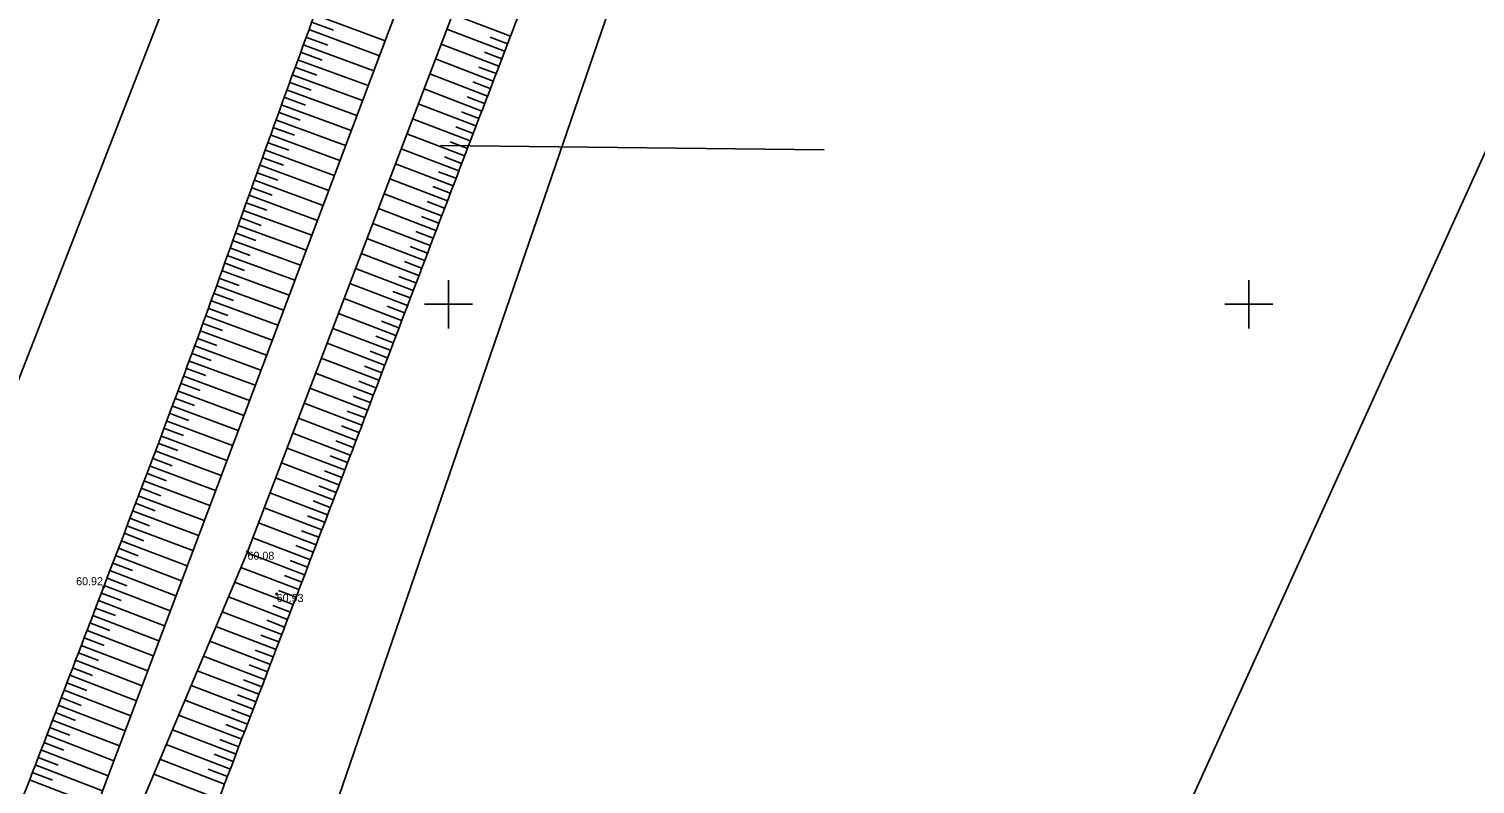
# Model space of a CAD drawing. Extents: x 616607 to 617499, y 408385 to 409695.
# Drawn here: x 617123.8 to 617214.1, y 408870 to 408917.2 of the extents above; entities that cross this region are included whole.
import ezdxf

# ---------------------------------------------------------------- set-up
doc = ezdxf.new("R2010")
doc.units = 0
for name, color, linetype in [('DREN_VADP_####_####_#', 7, 'Continuous'), ('GEOD_ELEM_####_####_#', 7, 'Continuous'), ('HIDG_GRAV_####_####_#', 7, 'Continuous'), ('RAMI_PLAN_####_TKST_#', 7, 'Continuous'), ('RAMI_UZMR_####_####_#', 7, 'Continuous'), ('RELJ_AATZ_####_TKST_#', 7, 'Continuous'), ('RELJ_ELEM_####_####_#', 7, 'Continuous'), ('RELJ_NOGA_####_####_#', 7, 'Continuous')]:
    doc.layers.add(name, color=color, linetype=linetype)

# ---------------------------------------------------------------- blocks, each defined once
blk = doc.blocks.new('PKT')
at = {"layer": 'RELJ_ELEM_####_####_#'}
blk.add_circle((0, 0), 0.05, dxfattribs=at)
blk = doc.blocks.new('KRUSTS')
at = {"layer": 'GEOD_ELEM_####_####_#'}
for p, q in [((0, 1.5), (0, 0)), ((-1.5, 0), (0, 0)), ((0, 0), (0, -1.5)), ((0, 0), (1.5, 0))]:
    blk.add_line(p, q, dxfattribs=at)

msp = doc.modelspace()

# ---------------------------------------------------------------- linework, layer by layer
at = {"layer": 'DREN_VADP_####_####_#'}
msp.add_lwpolyline([(617149.515, 408909.922), (617173.463, 408909.645)], dxfattribs=at)
at = {"layer": 'HIDG_GRAV_####_####_#'}
msp.add_lwpolyline([(616957.708, 408604.801), (616964.717, 408618.582), (616997.814, 408672.816), (617082.506, 408751.106), (617088.497, 408760.889), (617116.937, 408835.934), (617137.451, 408884.548), (617152.78, 408924.733), (617163.79, 408955.542), (617160.997, 408956.152), (617115.742, 408836.043), (617088.001, 408760.943), (617081.506, 408751.106), (616997.147, 408673.705), (616963.717, 408618.582), (616956.708, 408604.801)], dxfattribs=at)
at = {"layer": 'RAMI_PLAN_####_TKST_#'}
msp.add_line((617158.243, 408784.967), (617287, 409068.676), dxfattribs=at)
at = {"layer": 'RAMI_UZMR_####_####_#'}
for points in [[(617191.828, 409115.62), (617145.545, 408952.8), (617072.809, 408766.141), (616965.332, 408652.076), (616939.432, 408594.661), (616924.839, 408592.467), (616706.433, 408526.081), (616666.426, 408467.691)], [(616666.426, 408467.691), (616675.529, 408457.882), (616687.228, 408463.356), (616723.888, 408465.775), (616753.554, 408507.232), (616948.282, 408568.831), (616981.528, 408608.531), (617014.563, 408672.892), (617101.571, 408748.246), (617213.472, 409074.039)]]:
    msp.add_lwpolyline(points, dxfattribs=at)
at = {"layer": 'RELJ_NOGA_####_####_#'}
for p, q in [((617141.507, 408917.605), (617142.815, 408917.122)), ((617141.68, 408918.074), (617146.042, 408916.461)), ((617153.87, 408916.742), (617150.261, 408918.128)), ((617141.105, 408916.514), (617141.106, 408916.514)), ((617141.161, 408916.667), (617142.467, 408916.185)), ((617141.278, 408916.983), (617141.278, 408916.983)), ((617141.334, 408917.136), (617145.691, 408915.528)), ((617153.512, 408915.809), (617149.904, 408917.193)), ((617153.691, 408916.275), (617152.608, 408916.691)), ((617140.815, 408915.728), (617142.12, 408915.248)), ((617140.932, 408916.045), (617140.932, 408916.045)), ((617140.988, 408916.197), (617145.339, 408914.594)), ((617153.153, 408914.875), (617149.547, 408916.258)), ((617153.332, 408915.342), (617152.25, 408915.757)), ((617140.47, 408914.79), (617141.772, 408914.311)), ((617140.587, 408915.107), (617140.587, 408915.107)), ((617140.643, 408915.259), (617144.987, 408913.66)), ((617140.759, 408915.576), (617140.76, 408915.576)), ((617152.795, 408913.941), (617149.191, 408915.323)), ((617152.974, 408914.408), (617151.893, 408914.823)), ((617140.125, 408913.851), (617141.425, 408913.374)), ((617140.242, 408914.168), (617140.242, 408914.168)), ((617140.298, 408914.32), (617144.635, 408912.726)), ((617140.414, 408914.637), (617140.415, 408914.637)), ((617152.437, 408913.008), (617148.834, 408914.389)), ((617152.616, 408913.474), (617151.535, 408913.889)), ((617139.781, 408912.912), (617141.079, 408912.436)), ((617139.897, 408913.229), (617139.897, 408913.229)), ((617139.953, 408913.382), (617144.283, 408911.792)), ((617140.069, 408913.699), (617140.07, 408913.698)), ((617152.08, 408912.074), (617148.478, 408913.454)), ((617152.259, 408912.541), (617151.178, 408912.955)), ((617139.553, 408912.29), (617139.553, 408912.29)), ((617139.609, 408912.443), (617143.931, 408910.858)), ((617139.725, 408912.76), (617139.726, 408912.76)), ((617151.722, 408911.14), (617148.121, 408912.519)), ((617151.901, 408911.607), (617150.82, 408912.021)), ((617139.209, 408911.351), (617139.209, 408911.351)), ((617139.265, 408911.504), (617143.579, 408909.924)), ((617139.381, 408911.821), (617139.382, 408911.821)), ((617139.436, 408911.973), (617140.732, 408911.499)), ((617151.364, 408910.206), (617147.764, 408911.584)), ((617138.865, 408910.412), (617138.865, 408910.412)), ((617138.921, 408910.565), (617143.227, 408908.988)), ((617139.037, 408910.882), (617139.038, 408910.882)), ((617139.093, 408911.034), (617140.386, 408910.561)), ((617151.007, 408909.272), (617147.408, 408910.65)), ((617151.543, 408910.673), (617150.463, 408911.087)), ((617138.521, 408909.473), (617138.521, 408909.473)), ((617138.577, 408909.626), (617142.874, 408908.052)), ((617138.693, 408909.943), (617138.694, 408909.943)), ((617138.749, 408910.095), (617140.039, 408909.623)), ((617150.65, 408908.338), (617147.052, 408909.715)), ((617151.186, 408909.739), (617150.106, 408910.152)), ((617138.178, 408908.534), (617138.178, 408908.534)), ((617138.233, 408908.687), (617142.522, 408907.118)), ((617138.349, 408909.004), (617138.35, 408909.003)), ((617138.405, 408909.156), (617139.693, 408908.685)), ((617150.292, 408907.404), (617146.695, 408908.78)), ((617150.828, 408908.805), (617149.749, 408909.218)), ((617137.834, 408907.595), (617137.834, 408907.595)), ((617137.89, 408907.748), (617142.169, 408906.182)), ((617138.006, 408908.065), (617138.007, 408908.064)), ((617138.062, 408908.217), (617139.347, 408907.747)), ((617149.935, 408906.47), (617146.338, 408907.846)), ((617150.471, 408907.871), (617149.391, 408908.284)), ((617137.491, 408906.656), (617137.491, 408906.656)), ((617137.546, 408906.808), (617141.817, 408905.246)), ((617137.662, 408907.125), (617137.663, 408907.125)), ((617137.718, 408907.278), (617139.001, 408906.809)), ((617149.578, 408905.536), (617145.982, 408906.911)), ((617150.114, 408906.937), (617149.034, 408907.35)), ((617137.147, 408905.717), (617137.147, 408905.717)), ((617137.203, 408905.869), (617141.464, 408904.311)), ((617137.319, 408906.186), (617137.32, 408906.186)), ((617137.375, 408906.339), (617138.654, 408905.871)), ((617149.221, 408904.602), (617145.625, 408905.976)), ((617149.756, 408906.003), (617148.678, 408906.416)), ((617136.804, 408904.778), (617136.804, 408904.778)), ((617136.859, 408904.93), (617141.112, 408903.375)), ((617136.975, 408905.247), (617136.976, 408905.247)), ((617137.031, 408905.4), (617138.308, 408904.933)), ((617148.864, 408903.668), (617145.269, 408905.042)), ((617149.399, 408905.069), (617148.321, 408905.481)), ((617136.516, 408903.991), (617140.759, 408902.439)), ((617136.632, 408904.308), (617136.633, 408904.308)), ((617136.688, 408904.46), (617137.962, 408903.994)), ((617148.507, 408902.734), (617144.912, 408904.107)), ((617149.042, 408904.135), (617147.964, 408904.547)), ((617136.172, 408903.052), (617140.406, 408901.503)), ((617136.288, 408903.369), (617136.289, 408903.369)), ((617136.344, 408903.521), (617137.616, 408903.056)), ((617136.46, 408903.838), (617136.46, 408903.838)), ((617148.15, 408901.8), (617144.556, 408903.172)), ((617148.685, 408903.201), (617147.607, 408903.613)), ((617135.829, 408902.113), (617140.053, 408900.565)), ((617135.945, 408902.43), (617135.946, 408902.429)), ((617136.001, 408902.582), (617137.269, 408902.117)), ((617136.117, 408902.899), (617136.117, 408902.899)), ((617147.793, 408900.865), (617144.199, 408902.238)), ((617148.328, 408902.267), (617147.25, 408902.679)), ((617135.485, 408901.174), (617139.7, 408899.629)), ((617135.601, 408901.491), (617135.602, 408901.49)), ((617135.657, 408901.643), (617136.923, 408901.179)), ((617135.773, 408901.96), (617135.773, 408901.96)), ((617147.436, 408899.931), (617143.843, 408901.304)), ((617147.972, 408901.333), (617146.893, 408901.744)), ((617135.257, 408900.552), (617135.258, 408900.552)), ((617135.312, 408900.704), (617136.576, 408900.241)), ((617135.429, 408901.021), (617135.429, 408901.021)), ((617147.08, 408898.997), (617143.486, 408900.369)), ((617147.615, 408900.398), (617146.537, 408900.81)), ((617134.912, 408899.613), (617134.913, 408899.613)), ((617134.968, 408899.765), (617136.229, 408899.303)), ((617135.084, 408900.082), (617135.085, 408900.082)), ((617135.14, 408900.235), (617139.347, 408898.691)), ((617146.723, 408898.063), (617143.13, 408899.434)), ((617147.258, 408899.464), (617146.18, 408899.876)), ((617134.567, 408898.674), (617134.568, 408898.674)), ((617134.623, 408898.827), (617135.882, 408898.364)), ((617134.74, 408899.144), (617134.74, 408899.144)), ((617134.796, 408899.296), (617138.994, 408897.755)), ((617146.367, 408897.129), (617142.773, 408898.5)), ((617146.901, 408898.53), (617145.823, 408898.941)), ((617134.222, 408897.736), (617134.223, 408897.735)), ((617134.278, 408897.888), (617135.534, 408897.426)), ((617134.395, 408898.205), (617134.395, 408898.205)), ((617134.451, 408898.357), (617138.641, 408896.817)), ((617146.01, 408896.194), (617142.417, 408897.565)), ((617146.545, 408897.596), (617145.467, 408898.007)), ((617133.877, 408896.797), (617133.878, 408896.797)), ((617133.933, 408896.95), (617135.187, 408896.488)), ((617134.05, 408897.267), (617134.05, 408897.266)), ((617134.106, 408897.419), (617138.288, 408895.88)), ((617146.188, 408896.661), (617145.11, 408897.073)), ((617133.531, 408895.859), (617133.532, 408895.859)), ((617133.587, 408896.011), (617134.838, 408895.55)), ((617133.704, 408896.328), (617133.704, 408896.328)), ((617133.76, 408896.481), (617137.934, 408894.942)), ((617145.654, 408895.26), (617142.06, 408896.631)), ((617145.832, 408895.727), (617144.754, 408896.138)), ((617133.185, 408894.921), (617133.186, 408894.921)), ((617133.241, 408895.073), (617134.49, 408894.612)), ((617133.358, 408895.39), (617133.358, 408895.39)), ((617133.414, 408895.542), (617137.581, 408894.003)), ((617145.297, 408894.326), (617141.704, 408895.697)), ((617145.475, 408894.793), (617144.397, 408895.204)), ((617132.838, 408893.983), (617132.839, 408893.983)), ((617132.894, 408894.135), (617134.141, 408893.674)), ((617133.011, 408894.452), (617133.012, 408894.452)), ((617133.068, 408894.604), (617137.227, 408893.065)), ((617144.94, 408893.391), (617141.348, 408894.762)), ((617145.119, 408893.859), (617144.041, 408894.27)), ((617132.49, 408893.045), (617132.491, 408893.045)), ((617132.547, 408893.198), (617133.792, 408892.736)), ((617132.664, 408893.514), (617132.664, 408893.514)), ((617132.72, 408893.666), (617136.874, 408892.129)), ((617144.584, 408892.457), (617140.991, 408893.828)), ((617144.762, 408892.924), (617143.684, 408893.336)), ((617132.199, 408892.26), (617133.442, 408891.798)), ((617132.316, 408892.577), (617132.317, 408892.577)), ((617132.373, 408892.729), (617136.521, 408891.19)), ((617144.227, 408891.523), (617140.635, 408892.894)), ((617144.406, 408891.99), (617143.328, 408892.401)), ((617131.85, 408891.323), (617133.092, 408890.861)), ((617131.968, 408891.639), (617131.968, 408891.639)), ((617132.024, 408891.791), (617136.167, 408890.251)), ((617132.142, 408892.108), (617132.143, 408892.108)), ((617143.871, 408890.589), (617140.278, 408891.959)), ((617144.049, 408891.056), (617142.971, 408891.467)), ((617131.501, 408890.386), (617132.741, 408889.923)), ((617131.619, 408890.702), (617131.619, 408890.702)), ((617131.676, 408890.854), (617135.813, 408889.311)), ((617131.794, 408891.171), (617131.794, 408891.17)), ((617143.514, 408889.654), (617139.922, 408891.025)), ((617143.693, 408890.121), (617142.615, 408890.533)), ((617131.151, 408889.449), (617132.39, 408888.985)), ((617131.269, 408889.765), (617131.269, 408889.765)), ((617131.326, 408889.917), (617135.458, 408888.371)), ((617131.444, 408890.234), (617131.445, 408890.233)), ((617143.158, 408888.72), (617139.566, 408890.091)), ((617143.336, 408889.187), (617142.258, 408889.598)), ((617130.8, 408888.513), (617132.038, 408888.048)), ((617130.919, 408888.829), (617130.919, 408888.829)), ((617130.975, 408888.981), (617135.106, 408887.435)), ((617131.094, 408889.297), (617131.095, 408889.297)), ((617142.801, 408887.786), (617139.209, 408889.156)), ((617142.98, 408888.253), (617141.902, 408888.664)), ((617130.567, 408887.893), (617130.568, 408887.892)), ((617130.624, 408888.044), (617134.752, 408886.496)), ((617130.743, 408888.361), (617130.744, 408888.36)), ((617142.445, 408886.851), (617138.853, 408888.222)), ((617142.623, 408887.319), (617141.545, 408887.73)), ((617130.215, 408886.957), (617130.215, 408886.956)), ((617130.272, 408887.108), (617134.397, 408885.554)), ((617130.391, 408887.424), (617130.392, 408887.424)), ((617130.448, 408887.576), (617131.686, 408887.111)), ((617142.088, 408885.917), (617138.496, 408887.288)), ((617142.267, 408886.384), (617141.189, 408886.795)), ((617129.862, 408886.021), (617129.862, 408886.021)), ((617129.92, 408886.173), (617134.044, 408884.616)), ((617130.039, 408886.489), (617130.04, 408886.488)), ((617130.096, 408886.641), (617131.334, 408886.174)), ((617141.732, 408884.983), (617138.14, 408886.353)), ((617141.91, 408885.45), (617140.832, 408885.861)), ((617129.508, 408885.086), (617129.509, 408885.086)), ((617129.566, 408885.237), (617133.689, 408883.674)), ((617129.685, 408885.553), (617129.686, 408885.553)), ((617129.743, 408885.705), (617130.98, 408885.237)), ((617141.375, 408884.049), (617137.784, 408885.419)), ((617141.554, 408884.516), (617140.476, 408884.927)), ((617129.153, 408884.151), (617129.154, 408884.151)), ((617129.211, 408884.302), (617133.335, 408882.735)), ((617129.331, 408884.618), (617129.332, 408884.618)), ((617129.389, 408884.77), (617130.626, 408884.301)), ((617141.019, 408883.114), (617137.425, 408884.486)), ((617141.197, 408883.581), (617140.12, 408883.993)), ((617128.798, 408883.216), (617128.798, 408883.216)), ((617128.855, 408883.368), (617132.981, 408881.796)), ((617128.976, 408883.683), (617128.976, 408883.683)), ((617129.033, 408883.835), (617130.271, 408883.365)), ((617140.662, 408882.18), (617137.036, 408883.564)), ((617128.441, 408882.282), (617128.441, 408882.282)), ((617128.499, 408882.434), (617132.627, 408880.856)), ((617128.619, 408882.749), (617128.62, 408882.749)), ((617128.677, 408882.901), (617129.915, 408882.428)), ((617140.306, 408881.246), (617136.647, 408882.642)), ((617140.84, 408882.647), (617139.757, 408883.06)), ((617128.083, 408881.348), (617128.083, 408881.348)), ((617128.141, 408881.5), (617132.273, 408879.918)), ((617128.262, 408881.815), (617128.263, 408881.815)), ((617128.32, 408881.967), (617129.559, 408881.492)), ((617139.949, 408880.312), (617136.258, 408881.721)), ((617140.484, 408881.713), (617139.391, 408882.13)), ((617127.725, 408880.414), (617127.725, 408880.414)), ((617127.783, 408880.566), (617131.92, 408878.98)), ((617127.904, 408880.881), (617127.905, 408880.881)), ((617127.962, 408881.033), (617129.202, 408880.557)), ((617139.592, 408879.377), (617135.869, 408880.799)), ((617140.127, 408880.779), (617139.025, 408881.199)), ((617127.366, 408879.481), (617127.367, 408879.481)), ((617127.425, 408879.632), (617131.567, 408878.042)), ((617127.546, 408879.948), (617127.547, 408879.947)), ((617127.604, 408880.099), (617128.846, 408879.622)), ((617139.235, 408878.443), (617135.48, 408879.877)), ((617139.771, 408879.844), (617138.658, 408880.269)), ((617127.066, 408878.699), (617131.214, 408877.106)), ((617127.187, 408879.014), (617127.188, 408879.014)), ((617127.245, 408879.166), (617128.489, 408878.688)), ((617138.879, 408877.509), (617135.091, 408878.956)), ((617139.414, 408878.91), (617138.292, 408879.339)), ((617126.707, 408877.766), (617130.86, 408876.168)), ((617126.828, 408878.081), (617126.829, 408878.08)), ((617126.887, 408878.232), (617128.132, 408877.753)), ((617127.008, 408878.547), (617127.008, 408878.547)), ((617138.522, 408876.575), (617134.702, 408878.034)), ((617139.057, 408877.976), (617137.926, 408878.408)), ((617126.348, 408876.832), (617130.507, 408875.23)), ((617126.469, 408877.148), (617126.47, 408877.147)), ((617126.528, 408877.299), (617127.774, 408876.819)), ((617126.649, 408877.614), (617126.649, 408877.614)), ((617138.165, 408875.641), (617134.314, 408877.113)), ((617138.7, 408877.042), (617137.559, 408877.478)), ((617125.988, 408875.899), (617130.154, 408874.294)), ((617126.11, 408876.214), (617126.111, 408876.214)), ((617126.168, 408876.366), (617127.417, 408875.885)), ((617126.289, 408876.681), (617126.29, 408876.681)), ((617137.808, 408874.707), (617133.925, 408876.191)), ((617138.343, 408876.108), (617137.193, 408876.547)), ((617125.628, 408874.966), (617129.801, 408873.355)), ((617125.75, 408875.281), (617125.751, 408875.281)), ((617125.808, 408875.433), (617127.059, 408874.95)), ((617125.93, 408875.748), (617125.93, 408875.748)), ((617137.451, 408873.772), (617133.536, 408875.269)), ((617137.986, 408875.174), (617136.826, 408875.617)), ((617125.39, 408874.349), (617125.391, 408874.348)), ((617125.448, 408874.5), (617126.701, 408874.016)), ((617125.57, 408874.815), (617125.57, 408874.815)), ((617137.094, 408872.838), (617133.147, 408874.348)), ((617137.629, 408874.239), (617136.459, 408874.687)), ((617125.029, 408873.416), (617125.03, 408873.415)), ((617125.088, 408873.567), (617126.343, 408873.082)), ((617125.21, 408873.882), (617125.21, 408873.882)), ((617125.268, 408874.033), (617129.448, 408872.42)), ((617136.736, 408871.904), (617132.758, 408873.426)), ((617137.272, 408873.305), (617136.093, 408873.756)), ((617124.669, 408872.483), (617124.67, 408872.483)), ((617124.727, 408872.634), (617125.985, 408872.148)), ((617124.849, 408872.949), (617124.849, 408872.949)), ((617124.908, 408873.101), (617129.095, 408871.482)), ((617136.379, 408870.97), (617132.369, 408872.504)), ((617136.915, 408872.371), (617135.726, 408872.826)), ((617124.308, 408871.55), (617124.309, 408871.55)), ((617124.367, 408871.702), (617125.626, 408871.214)), ((617124.489, 408872.017), (617124.489, 408872.016)), ((617124.547, 408872.168), (617128.742, 408870.546)), ((617136.022, 408870.036), (617131.98, 408871.583)), ((617136.558, 408871.437), (617135.359, 408871.896)), ((617123.947, 408870.618), (617123.948, 408870.617)), ((617124.006, 408870.769), (617125.268, 408870.281)), ((617124.128, 408871.084), (617124.128, 408871.084)), ((617124.186, 408871.235), (617128.389, 408869.609)), ((617135.664, 408869.103), (617131.591, 408870.661)), ((617136.2, 408870.503), (617134.993, 408870.966)), ((617123.825, 408870.303), (617128.036, 408868.672))]:
    msp.add_line(p, q, dxfattribs=at)
for points in [[(616952.11, 408607.531), (616956.151, 408614.166), (616960.13, 408620.838), (616964.128, 408627.499), (616969.357, 408636.209), (616974.533, 408644.951), (616979.755, 408653.666), (616982.367, 408658.027), (616985.018, 408662.364), (616987.709, 408666.677), (616989.056, 408668.838), (616990.438, 408670.976), (616991.835, 408673.105), (616992.534, 408674.172), (616993.243, 408675.231), (616993.95, 408676.293), (616994.657, 408677.356), (616995.377, 408678.409), (616996.104, 408679.46), (616998.164, 408682.436), (617000.493, 408685.215), (617003.037, 408687.806), (617005.59, 408690.406), (617008.236, 408692.879), (617011.016, 408695.214), (617013.812, 408697.562), (617016.632, 408699.88), (617019.423, 408702.233), (617020.817, 408703.408), (617022.221, 408704.57), (617023.595, 408705.77), (617024.962, 408706.965), (617026.3, 408708.194), (617027.642, 408709.417), (617031.797, 408713.202), (617035.92, 408717.024), (617040.083, 408720.8), (617044.243, 408724.572), (617048.471, 408728.267), (617052.642, 408732.025), (617056.824, 408735.794), (617060.981, 408739.59), (617065.093, 408743.436), (617067.159, 408745.369), (617069.191, 408747.335), (617071.208, 408749.318), (617072.22, 408750.314), (617073.221, 408751.32), (617074.226, 408752.322), (617075.234, 408753.328), (617076.23, 408754.338), (617077.212, 408755.375), (617081.698, 408760.112), (617084.989, 408765.985), (617087.243, 408772.093), (617089.541, 408778.321), (617091.528, 408784.634), (617093.829, 408790.846), (617099.646, 408806.547), (617105.384, 408822.279), (617111.331, 408837.932), (617116.967, 408852.766), (617122.795, 408867.526), (617128.465, 408882.346), (617134.52, 408898.17), (617140.109, 408914.165), (617146.15, 408930), (617147.203, 408932.762), (617148.413, 408935.46), (617149.608, 408938.162), (617150.805, 408940.87), (617152.218, 408943.437), (617153.491, 408946.151), (617155.134, 408949.654), (617156.252, 408953.338), (617157.386, 408956.937), (617157.388, 408956.942), (617157.376, 408956.956), (617157.382, 408956.955), (617158.587, 408956.687), (617159.792, 408956.42), (617160.997, 408956.152)], [(617163.79, 408955.542), (617165.45, 408955.194), (617167.11, 408954.846), (617168.77, 408954.498), (617168.913, 408954.468), (617169.034, 408954.324), (617169.074, 408954.183), (617169.128, 408953.99), (617169.08, 408953.773), (617169.007, 408953.587), (617168.835, 408953.148), (617168.665, 408952.708), (617168.483, 408952.272), (617167.485, 408949.894), (617166.495, 408947.512), (617165.486, 408945.138), (617164.477, 408942.762), (617163.444, 408940.395), (617162.435, 408938.019), (617160.416, 408933.265), (617158.392, 408928.513), (617156.542, 408923.692), (617150.713, 408908.507), (617144.931, 408893.305), (617139.111, 408878.118), (617136.201, 408870.523), (617133.294, 408862.928), (617130.378, 408855.336), (617127.463, 408847.744), (617124.504, 408840.168), (617121.547, 408832.592), (617116.624, 408819.98), (617111.621, 408807.399), (617106.663, 408794.801), (617101.918, 408782.741), (617097.386, 408770.604), (617092.68, 408758.522), (617091.748, 408756.128), (617090.638, 408753.8), (617089.099, 408751.701), (617087.891, 408750.055), (617086.512, 408748.607), (617085.075, 408747.191), (617082.094, 408744.254), (617079.138, 408741.303), (617076.078, 408738.453), (617073.02, 408735.605), (617069.97, 408732.751), (617066.861, 408729.96), (617060.644, 408724.38), (617054.349, 408718.89), (617048.124, 408713.32), (617041.902, 408707.753), (617035.717, 408702.149), (617029.576, 408696.491), (617026.506, 408693.662), (617023.563, 408690.704), (617020.596, 408687.763), (617017.626, 408684.818), (617014.683, 408681.855), (617011.931, 408678.697), (617008.517, 408674.776), (617005.359, 408670.661), (617002.288, 408666.476), (616999.318, 408662.428), (616996.36, 408658.374), (616993.424, 408654.302), (616990.492, 408650.235), (616987.575, 408646.161), (616984.691, 408642.059), (616983.288, 408640.063), (616981.951, 408638.02), (616980.703, 408635.922), (616979.453, 408633.819), (616978.237, 408631.7), (616977.033, 408629.572), (616975.83, 408627.444), (616974.65, 408625.305), (616973.452, 408623.174), (616972.259, 408621.052), (616970.984, 408618.974), (616969.729, 408616.893), (616969.613, 408616.701), (616969.41, 408616.592), (616969.29, 408616.383), (616968.995, 408615.872), (616968.948, 408615.291), (616969.02, 408614.761), (616969.09, 408614.251), (616969.19, 408613.683), (616969.493, 408613.251)]]:
    msp.add_open_spline(points, degree=3, dxfattribs=at)

# ---------------------------------------------------------------- block references
at = {"layer": 'GEOD_ELEM_####_####_#'}
for p in [(617150, 408900), (617200, 408900)]:
    msp.add_blockref('KRUSTS', p, dxfattribs=at)
at = {"layer": 'RELJ_ELEM_####_####_#'}
for p in [(617137.451, 408884.548), (617128.465, 408882.346), (617139.272, 408881.913)]:
    msp.add_blockref('PKT', p, dxfattribs=at)

# ---------------------------------------------------------------- texts
at = {"layer": 'RELJ_AATZ_####_TKST_#'}
for s, p in [('60.08', (617137.451, 408884.048)), ('60.92', (617126.745, 408882.457)), ('60.93', (617139.272, 408881.413))]:
    msp.add_text(s, height=0.5, dxfattribs=at).set_placement(p)

doc.saveas('drawing.dxf')
